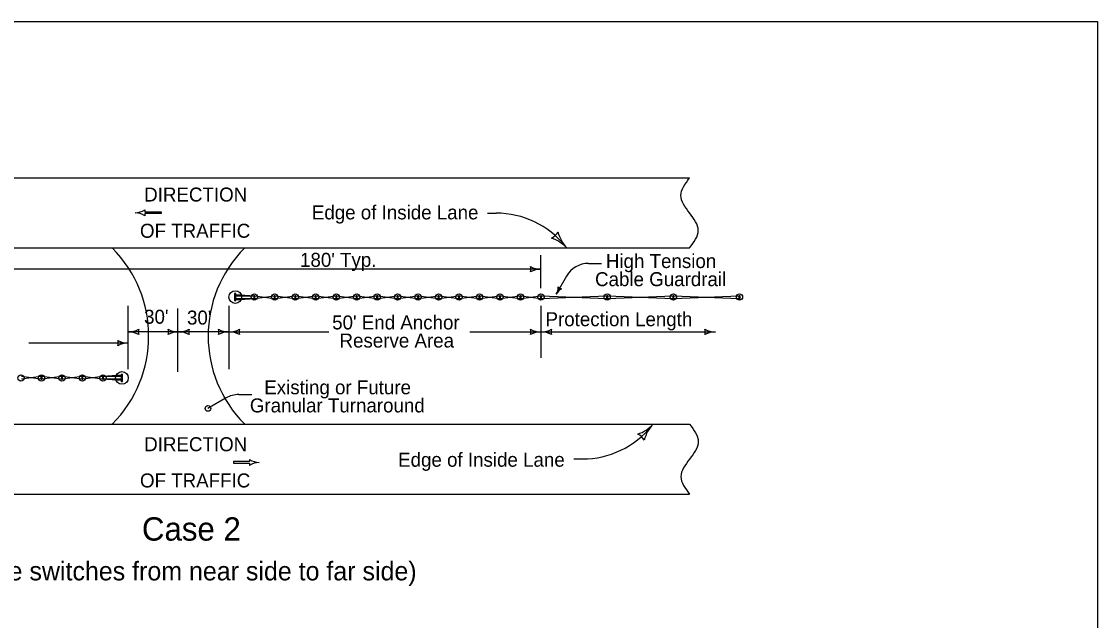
# Model space of a CAD drawing. Extents: x 10133 to 81668, y 7924 to 11018.
# Drawn here: x 12346 to 13268, y 9431 to 9944 of the extents above; entities that cross this region are included whole.
import ezdxf

# ---------------------------------------------------------------- set-up
doc = ezdxf.new("R2010")
doc.units = 0
for name, color, linetype in [('dsnCellElements', 7, 'Continuous'), ('DsnShtRevisedText', 7, 'Continuous'), ('dsnStdDimension', 7, 'Continuous'), ('Level 8', 7, 'Continuous'), ('SheetBorder', 7, 'Continuous')]:
    doc.layers.add(name, color=color, linetype=linetype)

msp = doc.modelspace()

# ---------------------------------------------------------------- linework, layer by layer
at = {"layer": 'dsnCellElements'}
for p, q in [((12528.75, 9710.23), (12545.51, 9709.05)), ((12528.75, 9709.05), (12544.58, 9709.05)), ((12545.51, 9706.8), (12562.09, 9709.05)), ((12545.51, 9709.05), (12562.09, 9706.8)), ((12563.03, 9706.8), (12579.66, 9709.05)), ((12563.03, 9709.05), (12579.66, 9706.8)), ((12580.61, 9706.8), (12597.19, 9709.05)), ((12580.61, 9709.05), (12597.19, 9706.8)), ((12598.13, 9706.8), (12614.76, 9709.05)), ((12598.13, 9709.05), (12614.76, 9706.8)), ((12615.71, 9706.8), (12632.29, 9709.05)), ((12615.71, 9709.05), (12632.29, 9706.8)), ((12633.23, 9706.8), (12649.86, 9709.05)), ((12633.23, 9709.05), (12649.86, 9706.8)), ((12650.8, 9709.05), (12667.38, 9706.8)), ((12650.8, 9706.8), (12667.38, 9709.05)), ((12668.32, 9706.8), (12684.95, 9709.05)), ((12668.32, 9709.05), (12684.95, 9706.8)), ((12685.89, 9709.05), (12702.47, 9706.79)), ((12685.89, 9706.8), (12702.47, 9709.04)), ((12703.41, 9706.79), (12720.04, 9709.05)), ((12703.41, 9709.04), (12720.04, 9706.8)), ((12720.98, 9709.05), (12737.56, 9706.79)), ((12720.98, 9706.8), (12737.56, 9709.04)), ((12738.5, 9706.79), (12755.13, 9709.05)), ((12738.5, 9709.04), (12755.13, 9706.8)), ((12756.07, 9709.05), (12772.65, 9706.79)), ((12756.07, 9706.8), (12772.65, 9709.04)), ((12773.59, 9706.79), (12790.22, 9709.05)), ((12773.59, 9709.04), (12790.22, 9706.8)), ((12791.16, 9706.8), (12846.92, 9709.05)), ((12791.16, 9709.05), (12846.92, 9706.8)), ((12847.86, 9706.8), (12903.63, 9709.05)), ((12847.86, 9709.05), (12903.63, 9706.8)), ((12904.57, 9706.8), (12960.33, 9709.05)), ((12904.57, 9709.05), (12960.33, 9706.8)), ((12528.75, 9706.8), (12544.58, 9706.8)), ((12528.75, 9705.61), (12545.51, 9706.8)), ((12362.22, 9639.72), (12345.59, 9637.47)), ((12362.22, 9637.47), (12345.59, 9639.72)), ((12379.74, 9639.72), (12363.16, 9637.47)), ((12379.74, 9637.47), (12363.16, 9639.72)), ((12397.32, 9639.72), (12380.69, 9637.47)), ((12397.32, 9637.47), (12380.69, 9639.72)), ((12414.84, 9639.72), (12398.26, 9637.47)), ((12414.84, 9637.47), (12398.26, 9639.72)), ((12431.6, 9640.91), (12414.84, 9639.72)), ((12431.6, 9636.29), (12414.84, 9637.47)), ((12431.6, 9639.72), (12415.77, 9639.72)), ((12431.6, 9637.47), (12415.77, 9637.47))]:
    msp.add_line(p, q, dxfattribs=at)
for points in [[(12528.14, 9710.92), (12528.14, 9704.92), (12529.36, 9704.92), (12529.36, 9710.92)], [(12544.57, 9709.05), (12544.57, 9706.8), (12545.51, 9706.8), (12545.51, 9709.05)], [(12562.09, 9709.05), (12562.09, 9706.8), (12563.03, 9706.8), (12563.03, 9709.05)], [(12579.67, 9709.05), (12579.67, 9706.8), (12580.61, 9706.8), (12580.61, 9709.05)], [(12597.19, 9709.05), (12597.19, 9706.8), (12598.13, 9706.8), (12598.13, 9709.05)], [(12614.77, 9709.05), (12614.77, 9706.8), (12615.71, 9706.8), (12615.71, 9709.05)], [(12632.29, 9709.05), (12632.29, 9706.8), (12633.23, 9706.8), (12633.23, 9709.05)], [(12649.86, 9709.05), (12649.86, 9706.8), (12650.8, 9706.8), (12650.8, 9709.05)], [(12667.38, 9709.05), (12667.38, 9706.8), (12668.32, 9706.8), (12668.32, 9709.05)], [(12684.95, 9709.05), (12684.95, 9706.8), (12685.89, 9706.8), (12685.89, 9709.05)], [(12702.47, 9709.04), (12702.47, 9706.79), (12703.41, 9706.79), (12703.41, 9709.04)], [(12720.04, 9709.05), (12720.04, 9706.8), (12720.98, 9706.8), (12720.98, 9709.05)], [(12737.56, 9709.04), (12737.56, 9706.79), (12738.5, 9706.79), (12738.5, 9709.04)], [(12755.13, 9709.05), (12755.13, 9706.8), (12756.07, 9706.8), (12756.07, 9709.05)], [(12772.65, 9709.04), (12772.65, 9706.79), (12773.59, 9706.79), (12773.59, 9709.04)], [(12790.22, 9709.05), (12790.22, 9706.8), (12791.16, 9706.8), (12791.16, 9709.05)], [(12790.22, 9709.05), (12790.22, 9706.8), (12791.16, 9706.8), (12791.16, 9709.05)], [(12846.92, 9709.05), (12846.92, 9706.8), (12847.86, 9706.8), (12847.86, 9709.05)], [(12846.92, 9709.05), (12846.92, 9706.8), (12847.86, 9706.8), (12847.86, 9709.05)], [(12903.63, 9709.05), (12903.63, 9706.8), (12904.57, 9706.8), (12904.57, 9709.05)], [(12903.63, 9709.05), (12903.63, 9706.8), (12904.57, 9706.8), (12904.57, 9709.05)], [(12960.33, 9709.05), (12960.33, 9706.8), (12961.27, 9706.8), (12961.27, 9709.05)], [(12363.16, 9637.47), (12363.16, 9639.72), (12362.22, 9639.72), (12362.22, 9637.47)], [(12380.68, 9637.47), (12380.68, 9639.72), (12379.74, 9639.72), (12379.74, 9637.47)], [(12398.26, 9637.47), (12398.26, 9639.72), (12397.32, 9639.72), (12397.32, 9637.47)], [(12415.78, 9637.47), (12415.78, 9639.72), (12414.84, 9639.72), (12414.84, 9637.47)], [(12432.21, 9635.6), (12432.21, 9641.6), (12430.99, 9641.6), (12430.99, 9635.6)]]:
    msp.add_lwpolyline(points, close=True, dxfattribs=at)
for centre, radius in [((12528.75, 9707.92), 5.4), ((12545.04, 9707.92), 2.66), ((12562.56, 9707.92), 2.66), ((12580.14, 9707.92), 2.66), ((12597.66, 9707.92), 2.66), ((12615.24, 9707.92), 2.66), ((12632.76, 9707.92), 2.66), ((12650.33, 9707.92), 2.66), ((12667.85, 9707.92), 2.66), ((12685.42, 9707.92), 2.66), ((12702.94, 9707.92), 2.66), ((12720.51, 9707.92), 2.66), ((12738.03, 9707.92), 2.66), ((12755.6, 9707.92), 2.66), ((12773.12, 9707.92), 2.66), ((12790.69, 9707.92), 2.66), ((12790.69, 9707.92), 2.66), ((12847.39, 9707.92), 2.66), ((12847.39, 9707.92), 2.66), ((12904.1, 9707.92), 2.66), ((12904.1, 9707.92), 2.66), ((12960.8, 9707.92), 2.66), ((12431.6, 9638.6), 5.4), ((12345.11, 9638.6), 2.66), ((12362.69, 9638.6), 2.66), ((12380.21, 9638.6), 2.66), ((12397.79, 9638.6), 2.66), ((12415.31, 9638.6), 2.66)]:
    msp.add_circle(centre, radius, dxfattribs=at)
at = {"layer": 'DsnShtRevisedText'}
for p, q in [((12451.2, 9782.68), (12451.2, 9780.9)), ((12443.1, 9780.14), (12443.1, 9780.14)), ((12451.2, 9780.9), (12465.17, 9780.9)), ((12465.17, 9779.38), (12451.2, 9779.38)), ((12451.2, 9779.38), (12451.2, 9777.6)), ((12465.17, 9780.9), (12465.17, 9779.38)), ((12744.87, 9779.82), (12752.31, 9779.82)), ((12790.69, 9715.44), (12790.69, 9743.71)), ((12831.39, 9736.73), (12842.64, 9736.73)), ((12461.14, 9731.71), (12169.66, 9731.71)), ((12790.69, 9731.71), (12461.14, 9731.71)), ((12812.59, 9725.92), (12803.71, 9710.28)), ((12437, 9646.12), (12437, 9700.4)), ((12523.35, 9700.4), (12523.35, 9646.12)), ((12790.69, 9700.4), (12790.69, 9655.78)), ((12479.6, 9643.85), (12479.6, 9698.12)), ((12523.35, 9678.09), (12437, 9678.09)), ((12523.35, 9678.09), (12608.79, 9678.09)), ((12729.76, 9678.09), (12790.69, 9678.09)), ((12790.69, 9678.09), (12812.97, 9678.09)), ((12812.97, 9678.09), (12940.1, 9678.09)), ((12437, 9668.43), (12351.91, 9668.43)), ((12520.85, 9621.52), (12505.3, 9612.47)), ((12531.71, 9624.35), (12542.96, 9624.35)), ((12541.05, 9566.95), (12527.08, 9566.95)), ((12527.08, 9566.95), (12527.08, 9565.43)), ((12527.08, 9565.43), (12541.05, 9565.43)), ((12541.05, 9568.73), (12541.05, 9566.95)), ((12541.05, 9565.43), (12541.05, 9563.65)), ((12549.14, 9566.19), (12549.14, 9566.19)), ((12818.78, 9569.16), (12826.23, 9569.16))]:
    msp.add_line(p, q, dxfattribs=at)
msp.add_circle((12505.3, 9612.47), 2.4, dxfattribs=at)
for centre, radius, start, end in [((12442.43, 9796.5), 16.37, 272.35199, 302.38203), ((12442.43, 9763.78), 16.37, 57.61797, 87.64801), ((12752.31, 9703.64), 76.18, 39.01063, 90), ((12794.32, 9769.82), 12.51, 295.26394, 330.73064), ((12836.51, 9772.04), 32.38, 194.9248, 222.99729), ((12789.15, 9727.88), 32.38, 42.99729, 71.06977), ((12347.79, 9674.49), 106.73, 315, 45), ((12612.26, 9674.49), 106.73, 135, 225), ((12831.39, 9714.97), 21.76, 90, 149.77566), ((12774.66, 9731.71), 7.39, 342.26665, 17.73335), ((12790.69, 9750.84), 19.13, 241.92751, 270), ((12790.69, 9712.59), 19.13, 90, 118.07249), ((12791.96, 9717.12), 13.6, 329.76864, 357.84113), ((12815.46, 9703.43), 13.6, 121.69616, 149.76864), ((12809.45, 9720.13), 5.25, 222.03529, 257.50199), ((12437, 9697.21), 19.13, 270, 298.07249), ((12437, 9658.96), 19.13, 61.92751, 90), ((12453.03, 9678.09), 7.39, 162.26665, 197.73335), ((12464.14, 9678.09), 7.39, 342.26665, 17.73335), ((12480.17, 9697.21), 19.13, 241.92751, 270), ((12480.17, 9658.96), 19.13, 90, 118.07249), ((12480.17, 9697.21), 19.13, 270, 298.07249), ((12480.17, 9658.96), 19.13, 61.92751, 90), ((12496.21, 9678.09), 7.39, 162.26665, 197.73335), ((12507.31, 9678.09), 7.39, 342.26665, 17.73335), ((12523.35, 9697.21), 19.13, 241.92751, 270), ((12523.35, 9658.96), 19.13, 90, 118.07249), ((12523.35, 9697.21), 19.13, 270, 298.07249), ((12523.35, 9658.96), 19.13, 61.92751, 90), ((12539.39, 9678.09), 7.39, 162.26665, 197.73335), ((12774.66, 9678.09), 7.39, 342.26665, 17.73335), ((12790.69, 9697.21), 19.13, 241.92751, 270), ((12790.69, 9658.96), 19.13, 90, 118.07249), ((12790.69, 9697.21), 19.13, 270, 298.07249), ((12790.69, 9658.96), 19.13, 61.92751, 90), ((12806.73, 9678.09), 7.39, 162.26665, 197.73335), ((12924.06, 9678.09), 7.39, 342.26665, 17.73335), ((12940.1, 9697.21), 19.13, 241.92751, 270), ((12940.1, 9658.96), 19.13, 90, 118.07249), ((12420.96, 9668.43), 7.39, 342.26665, 17.73335), ((12437, 9687.56), 19.13, 241.92751, 270), ((12437, 9649.31), 19.13, 90, 118.07249), ((12531.58, 9602.59), 21.76, 89.65652, 119.54435), ((12863.07, 9621.1), 32.38, 288.93023, 317.00271), ((12910.43, 9576.94), 32.38, 137.00271, 165.0752), ((12826.23, 9645.34), 76.18, 270, 320.98937), ((12868.23, 9579.16), 12.51, 29.26936, 64.73606), ((12549.81, 9582.55), 16.37, 237.61797, 267.64801), ((12549.81, 9549.83), 16.37, 92.35199, 122.38203)]:
    msp.add_arc(centre, radius, start, end, dxfattribs=at)
at = {"layer": 'dsnStdDimension'}
for p, q in [((12042.34, 9809.96), (12918, 9809.96)), ((12042.34, 9749.96), (12918, 9749.96)), ((12042.34, 9599.02), (12918, 9599.02)), ((12042.34, 9539.02), (12918, 9539.02))]:
    msp.add_line(p, q, dxfattribs=at)
for points in [[(12918, 9749.96), (12925.5, 9764.96), (12918, 9779.96), (12910.5, 9794.96), (12918, 9809.96)], [(12918, 9599.02), (12925.5, 9584.02), (12918, 9569.02), (12910.5, 9554.02), (12918, 9539.02)]]:
    msp.add_spline(points, degree=3, dxfattribs=at)
at = {"layer": 'SheetBorder'}
msp.add_lwpolyline([(10132.52, 9944.02), (13267.53, 9944.02), (13267.53, 7924.02), (10132.52, 7924.02)], close=True, dxfattribs=at)

# ---------------------------------------------------------------- texts
at = {"layer": 'DsnShtRevisedText'}
for s, p in [('DIRECTION', (12450.7, 9789.76)), ('Edge of Inside Lane', (12594.36, 9774.46)), ('OF TRAFFIC', (12447.09, 9758.7)), ("180' Typ.", (12584.23, 9733.8)), ('High Tension', (12846.31, 9732.77)), ('Cable Guardrail', (12837.02, 9717.24)), ("30'", (12450.61, 9685.05)), ("30'", (12487.37, 9684.33)), ("50' End Anchor", (12611.78, 9680.17)), ('Protection Length', (12794.58, 9682.95)), ('Reserve Area', (12618.06, 9664.64)), ('Existing or Future', (12553.55, 9624.59)), ('Granular Turnaround', (12541.23, 9609.06)), ('DIRECTION', (12450.7, 9575.81)), ('Edge of Inside Lane', (12668.28, 9562.52)), ('OF TRAFFIC', (12447.09, 9544.75))]:
    msp.add_text(s, height=12, dxfattribs=at).set_placement(p)
at = {"layer": 'Level 8'}
for s, height, p in [('Case 2', 20, (12448.76, 9499.19)), ('(Cable switches from near side to far side)', 16, (12283.4, 9465.12))]:
    msp.add_text(s, height=height, dxfattribs=at).set_placement(p)

doc.saveas('drawing.dxf')
